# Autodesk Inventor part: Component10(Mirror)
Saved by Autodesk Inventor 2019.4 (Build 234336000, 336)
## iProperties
Created: 2020-06
Part Number: Component10(Mirror)
Material: Generic
Document SubType Name: Modeling
Designer: Administrator
Density: 1 g/cm^3
Appearance: Default
Title: Component10(Mirror)
Author: Administrator
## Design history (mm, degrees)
